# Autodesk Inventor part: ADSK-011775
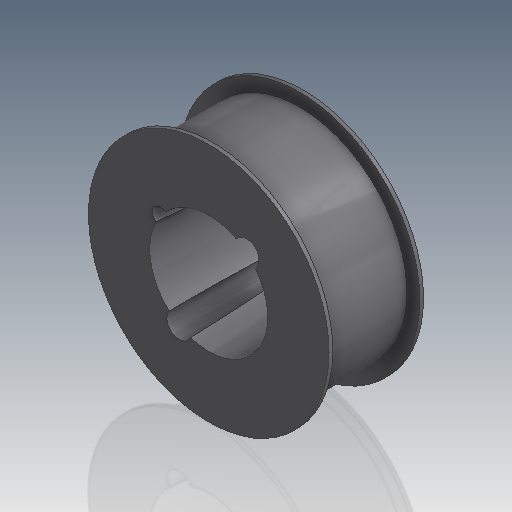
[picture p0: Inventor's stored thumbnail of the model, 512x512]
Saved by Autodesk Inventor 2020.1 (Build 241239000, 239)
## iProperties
Created: 1999-11
Part Number: ADSK-011775
Description: SPROCKET,TIMING,8MMX34T,1610BUSH
Document SubType Name: Modeling
Designer: mpflueger
Material: Acier doux
Density: 7.86 g/cm^3
Appearance: Metal-Steel(Polish)
Mass: 1282.89 g
Surface Area: 312.68 cm^2
Volume: 163.218 cm^3
Control State: 0
Checked Out: False
Last Check In By: cmcgourin
Last Check In Date: 1999-12-09
Master: False
Shininess: 60.0
Length Units: 11269
Angle Units: 11279
Time Units: 11290
Mass Units: 11283
Length Display Precision: 3
Angle Display Precision: 2
Compacted: True
Dimensions: 97x38,1x97 mm
Mass: 1,283 kg
VLT_Material: Acier doux
DocNumber: ADSK-011775.ipt
Folder: 01 - Themengebiete\Simplification\01 - Packaging machine\
VDS_Category: 3D Komponenten
Density: 7.86
Volumn: 131.38854252371846
Area: 299.6185747203996
PropertySet Name: Model Information
Author: mpflueger
Revision Number: -
Title: wheel
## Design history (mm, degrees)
node "Solide1"
  node "Extrusion1" dims "d0" = 38.1, "d1" = 0
  node "Extrusion3" dims "d8" = 1.5, "d9" = 0
  node "Extrusion4" dims "d10" = 1.5, "d11" = 0
sketch "Sketch1"
  geometry: C1 r 23.812 at (0, 0); C2 r 43.294 at (0, 0)
  constraints: 2 centre point, 1 coincident
  dimensions: "d2" = 47.625 diameter of C1; "d3" = 86.5886 diameter of C2
sketch "Sketch3"
  geometry: C1 r 43.294 at (0, 0) reference; C2 r 48.5 at (0, 0)
  constraints: 1 centre point, 1 coincident
  dimensions: "d7" = 97 diameter of C2
workplane "Arbeitsebene1"
feature "Flächenverjüngung1" dims angle "d14" = 4 deg
sketch "Skizze6"
  geometry: L1 (0, 0)-(0, 23.812); L2 (0, 0)-(15.306, 18.241); L3 (0, 0)-(-11.906, -20.622); L4 (0, 0)-(-19.506, 13.658); A1 r 23.812 centre (0, 0) between (0, 23.812) and (15.306, 18.241); 4 further points
  constraints: 8 end point, 4 coincident, 4 point on circle, 1 centre point, 1 vertical
  dimensions: "d15" = 47.625 diameter of A1; "d16" = 40 deg angle of L1 L2; "d17" = 170 deg angle of L3 L2; "d18" = 55 deg angle of L1 L4
hole "Bohrung1" sketch "Skizze6" diameter "d19" = 10; stored, may be unused: countersink angle "d23" = 90 deg, drill point angle "d25" = 118 deg; dims "d20" = 32, "d21" = 4, "d22" = 2, "d24" = 8
hole "Bohrung2" sketch "Skizze6" diameter "d26" = 6.6; stored, may be unused: countersink angle "d30" = 90 deg, drill point angle "d32" = 118 deg; dims "d27" = 32, "d28" = 4, "d29" = 2, "d31" = 8
node "Corps solides"
node "Corps surfaciques"
sketch "Sketch4"
  geometry: C1 r 43.294 at (0, 0) reference; C2 r 48.5 at (0, 0) reference
